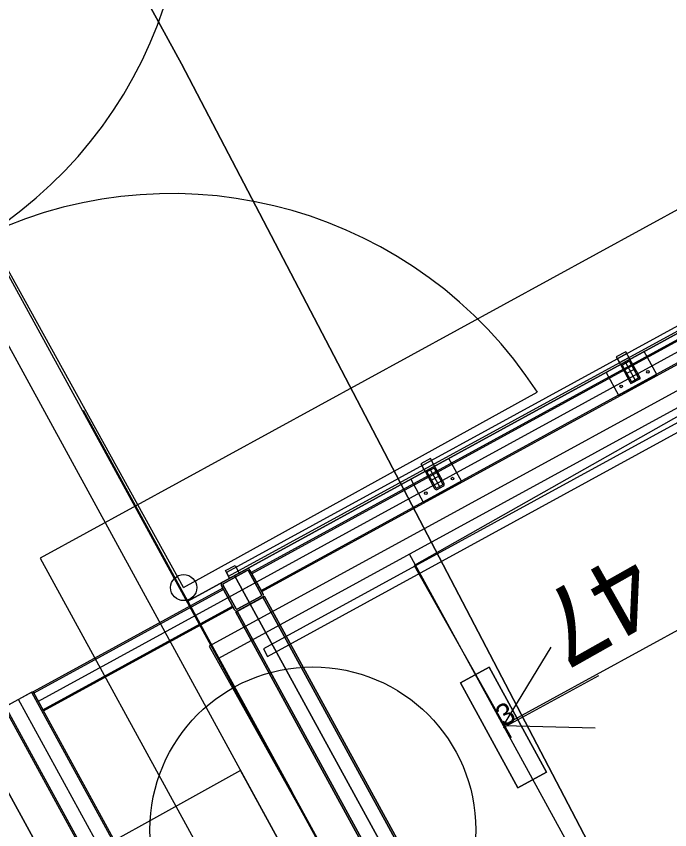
# Model space of a CAD drawing. Extents: x -783978 to -783565, y -1064821 to -1064596.
# Drawn here: x -783787.577 to -783784.57, y -1064693.706 to -1064689.961 of the extents above; entities that cross this region are included whole.
import ezdxf

# ---------------------------------------------------------------- set-up
doc = ezdxf.new("R2010")
doc.units = 0
for name, color, linetype in [('Default', 7, 'Continuous'), ('PS 01_01_10', 7, 'Continuous'), ('PS 01_02_501', 7, 'Continuous'), ('PS 01_02_502', 7, 'Continuous'), ('SO 01_20_01', 7, 'Continuous'), ('SO 01_50_01', 7, 'Continuous'), ('SO 01_74_01', 7, 'Continuous'), ('SO 01_79_02', 7, 'Continuous'), ('SO 01_86_03', 7, 'Continuous'), ('SO 01_86_04', 7, 'Continuous')]:
    doc.layers.add(name, color=color, linetype=linetype)

# ---------------------------------------------------------------- blocks, each defined once
blk = doc.blocks.new('POINT_DISPLAY')
at = {"layer": 'Default'}
blk.add_line((0, 0), (0, 0), dxfattribs=at)

msp = doc.modelspace()

# ---------------------------------------------------------------- linework, layer by layer
at = {"layer": 'PS 01_01_10'}
msp.add_lwpolyline([(-783718.9415, -1064658.9356), (-783725.9639, -1064662.6889), (-783732.3538, -1064665.9121), (-783735.2095, -1064660.6967), (-783789.362, -1064690.3481), (-783783.8255, -1064700.4409), (-783871.4362, -1064748.4249), (-783875.857, -1064749.8347)], dxfattribs=at)
at = {"layer": 'PS 01_02_501'}
msp.add_lwpolyline([(-783952.3105, -1064789.972), (-783925.027, -1064771.233), (-783922.857, -1064767.935), (-783921.1315, -1064767.225), (-783922.344, -1064769.056), (-783920.816, -1064771.043), (-783917.67, -1064770.417), (-783911.05, -1064766.471), (-783887.429, -1064753.525), (-783871.4362, -1064748.4249), (-783783.8277, -1064700.4386), (-783789.362, -1064690.3481), (-783735.2263, -1064660.7067), (-783727.1901, -1064659.072), (-783724.297, -1064658.4835), (-783715.521, -1064653.988), (-783697.391, -1064644.148), (-783676.268, -1064633.506), (-783655.138, -1064621.894)], dxfattribs=at)
at = {"layer": 'PS 01_02_502'}
msp.add_lwpolyline([(-783952.3105, -1064789.972), (-783925.027, -1064771.233), (-783922.857, -1064767.935), (-783921.1315, -1064767.225), (-783922.344, -1064769.056), (-783920.816, -1064771.043), (-783917.67, -1064770.417), (-783911.05, -1064766.471), (-783887.429, -1064753.525), (-783871.4362, -1064748.4249), (-783783.8277, -1064700.4386), (-783789.362, -1064690.3481), (-783735.2263, -1064660.7067), (-783727.1901, -1064659.072), (-783724.297, -1064658.4835), (-783715.521, -1064653.988), (-783697.391, -1064644.148), (-783676.268, -1064633.506), (-783655.138, -1064621.894)], dxfattribs=at)
at = {"layer": 'SO 01_20_01'}
for p, q in [((-783735.0054, -1064663.7532), (-783787.4671, -1064692.4555)), ((-783735.2041, -1064664.4318), (-783786.7885, -1064692.6541)), ((-783786.6445, -1064692.9173), (-783735.3233, -1064664.839)), ((-783738.0171, -1064666.3812), (-783786.4402, -1064692.874)), ((-783786.421, -1064692.9091), (-783737.9979, -1064666.4163)), ((-783737.8741, -1064667.2605), (-783785.3352, -1064693.2269)), ((-783787.4671, -1064692.4555), (-783785.8354, -1064695.4379)), ((-783784.9033, -1064694.0165), (-783785.7672, -1064692.4374)), ((-783786.7885, -1064692.6541), (-783786.6445, -1064692.9173)), ((-783786.4402, -1064692.874), (-783786.421, -1064692.9091)), ((-783785.3352, -1064693.2269), (-783785.1157, -1064692.866)), ((-783785.7805, -1064694.4964), (-783786.6445, -1064692.9173)), ((-783785.3352, -1064693.2269), (-783784.9129, -1064693.2366))]:
    msp.add_line(p, q, dxfattribs=at)
at = {"layer": 'SO 01_50_01'}
for p, q in [((-783786.7885, -1064692.6541), (-783725.4827, -1064659.1131)), ((-783786.7885, -1064692.6541), (-783782.4021, -1064690.2543)), ((-783786.7884, -1064692.6542), (-783782.402, -1064690.2544)), ((-783786.7884, -1064692.6542), (-783782.402, -1064690.2544)), ((-783786.3085, -1064693.5314), (-783787.2685, -1064691.7769))]:
    msp.add_line(p, q, dxfattribs=at)
for points in [[(-783789.5438, -1064687.9418), (-783784.9159, -1064696.417), (-783784.7774, -1064696.3413), (-783789.41, -1064687.8687)], [(-783786.5452, -1064693.4332), (-783787.5293, -1064693.9803), (-783787.1406, -1064694.6795), (-783786.1618, -1064694.1353)]]:
    msp.add_lwpolyline(points, close=True, dxfattribs=at)
msp.add_circle((-783786.2125, -1064693.7069), 0.75, dxfattribs=at)
at = {"layer": 'SO 01_74_01'}
for p, q in [((-783735.2185, -1064664.4055), (-783786.6099, -1064692.5222)), ((-783786.6003, -1064692.5398), (-783735.2089, -1064664.423)), ((-783783.9297, -1064691.1186), (-783786.4958, -1064692.5225)), ((-783783.9267, -1064691.1241), (-783786.4927, -1064692.528)), ((-783786.4508, -1064692.6047), (-783783.8847, -1064691.2008)), ((-783786.4478, -1064692.6102), (-783783.8817, -1064691.2063)), ((-783784.7724, -1064691.5055), (-783784.8162, -1064691.5295)), ((-783784.8162, -1064691.5295), (-783784.7971, -1064691.5646)), ((-783784.7676, -1064691.5143), (-783784.8115, -1064691.5383)), ((-783784.8019, -1064691.5558), (-783784.758, -1064691.5318)), ((-783784.7532, -1064691.5406), (-783784.7724, -1064691.5055)), ((-783784.758, -1064691.5318), (-783784.7676, -1064691.5143)), ((-783784.8115, -1064691.5383), (-783784.8019, -1064691.5558)), ((-783784.7971, -1064691.5646), (-783784.7532, -1064691.5406)), ((-783785.6716, -1064691.9975), (-783785.7155, -1064692.0215)), ((-783785.6668, -1064692.0063), (-783785.7107, -1064692.0303)), ((-783785.6524, -1064692.0326), (-783785.6716, -1064691.9975)), ((-783785.6572, -1064692.0238), (-783785.6668, -1064692.0063)), ((-783785.7155, -1064692.0215), (-783785.6963, -1064692.0566)), ((-783785.7107, -1064692.0303), (-783785.7011, -1064692.0478)), ((-783785.7011, -1064692.0478), (-783785.6572, -1064692.0238)), ((-783785.6963, -1064692.0566), (-783785.6524, -1064692.0326)), ((-783786.6147, -1064692.5135), (-783786.5708, -1064692.4895)), ((-783786.6147, -1064692.5135), (-783786.5708, -1064692.4895)), ((-783786.5708, -1064692.4895), (-783786.5516, -1064692.5245)), ((-783786.5708, -1064692.4895), (-783786.5516, -1064692.5245)), ((-783786.5955, -1064692.5485), (-783786.6147, -1064692.5135)), ((-783786.5955, -1064692.5485), (-783786.6147, -1064692.5135)), ((-783786.6099, -1064692.5222), (-783786.6003, -1064692.5398)), ((-783786.5516, -1064692.5245), (-783786.5955, -1064692.5485)), ((-783786.5516, -1064692.5245), (-783786.5955, -1064692.5485)), ((-783786.4958, -1064692.5225), (-783786.4478, -1064692.6102)), ((-783786.4927, -1064692.528), (-783786.4508, -1064692.6047)), ((-783786.6273, -1064692.5945), (-783787.5002, -1064693.072)), ((-783786.6243, -1064692.6), (-783787.4972, -1064693.0776)), ((-783786.5794, -1064692.6822), (-783786.6273, -1064692.5945)), ((-783786.5824, -1064692.6767), (-783786.6243, -1064692.6)), ((-783786.5674, -1064692.7041), (-783786.4358, -1064692.6321)), ((-783786.4358, -1064692.6321), (-783786.5674, -1064692.7041)), ((-783786.5603, -1064692.7003), (-783786.4428, -1064692.636)), ((-783786.4428, -1064692.636), (-783786.5603, -1064692.7003)), ((-783786.4428, -1064692.636), (-783785.4348, -1064694.4783)), ((-783785.4348, -1064694.4783), (-783786.4428, -1064692.636)), ((-783786.4358, -1064692.6321), (-783785.4278, -1064694.4744)), ((-783785.4278, -1064694.4744), (-783786.4358, -1064692.6321)), ((-783787.4553, -1064693.1542), (-783786.5824, -1064692.6767)), ((-783787.4523, -1064693.1598), (-783786.5794, -1064692.6822)), ((-783785.5594, -1064694.5464), (-783786.5674, -1064692.7041)), ((-783786.5674, -1064692.7041), (-783785.5594, -1064694.5464)), ((-783785.5524, -1064694.5426), (-783786.5603, -1064692.7003)), ((-783786.5603, -1064692.7003), (-783785.5524, -1064694.5426)), ((-783787.6328, -1064693.1424), (-783787.5012, -1064693.0704)), ((-783787.6272, -1064693.1393), (-783787.5067, -1064693.0734)), ((-783787.5067, -1064693.0734), (-783786.3776, -1064695.1372)), ((-783787.5012, -1064693.0704), (-783786.372, -1064695.1342)), ((-783787.5002, -1064693.072), (-783787.4523, -1064693.1598)), ((-783787.4972, -1064693.0776), (-783787.4553, -1064693.1542)), ((-783786.5036, -1064695.2062), (-783787.6328, -1064693.1424)), ((-783786.4981, -1064695.2032), (-783787.6272, -1064693.1393))]:
    msp.add_line(p, q, dxfattribs=at)
for points in [[(-783735.1681, -1064664.4976), (-783787.4762, -1064693.1159)], [(-783784.7615, -1064691.5451), (-783784.7888, -1064691.5601)], [(-783784.787, -1064691.5699), (-783784.7481, -1064691.641)], [(-783784.7585, -1064691.5507), (-783784.7857, -1064691.5656)], [(-783784.7751, -1064691.5526), (-783784.7271, -1064691.6403)], [(-783784.7153, -1064691.6231), (-783784.7542, -1064691.5519)], [(-783784.7097, -1064691.62), (-783784.7487, -1064691.5489)], [(-783784.7925, -1064691.5729), (-783784.7536, -1064691.644)], [(-783784.7292, -1064691.5845), (-783784.7731, -1064691.6085)], [(-783784.7438, -1064691.6423), (-783784.7165, -1064691.6273)], [(-783784.7408, -1064691.6478), (-783784.7135, -1064691.6329)], [(-783785.6607, -1064692.0371), (-783785.688, -1064692.052)], [(-783785.6577, -1064692.0426), (-783785.685, -1064692.0576)], [(-783785.6743, -1064692.0446), (-783785.6263, -1064692.1323)], [(-783785.6145, -1064692.115), (-783785.6534, -1064692.0439)], [(-783785.6089, -1064692.112), (-783785.6479, -1064692.0409)], [(-783785.6917, -1064692.0649), (-783785.6528, -1064692.136)], [(-783785.6862, -1064692.0618), (-783785.6473, -1064692.133)], [(-783785.6284, -1064692.0764), (-783785.6723, -1064692.1004)], [(-783785.643, -1064692.1342), (-783785.6157, -1064692.1193)], [(-783785.64, -1064692.1398), (-783785.6127, -1064692.1248)], [(-783786.5183, -1064692.5063), (-783786.6288, -1064692.5668)], [(-783786.6288, -1064692.5668), (-783786.5183, -1064692.5063)], [(-783786.5144, -1064692.5133), (-783786.625, -1064692.5738)], [(-783786.625, -1064692.5738), (-783786.5144, -1064692.5133)], [(-783785.4216, -1064694.642), (-783786.5736, -1064692.5365)], [(-783786.5736, -1064692.5365), (-783785.4216, -1064694.642)], [(-783786.5736, -1064692.5365), (-783786.5016, -1064692.6681)], [(-783786.4485, -1064692.6255), (-783786.509, -1064692.5149)], [(-783786.509, -1064692.5149), (-783786.4485, -1064692.6255)], [(-783786.4415, -1064692.6216), (-783786.502, -1064692.5111)], [(-783786.502, -1064692.5111), (-783786.4415, -1064692.6216)], [(-783786.6266, -1064692.5792), (-783786.5661, -1064692.6898)], [(-783786.5661, -1064692.6898), (-783786.6266, -1064692.5792)], [(-783786.4718, -1064692.5663), (-783786.6034, -1064692.6383)], [(-783786.6336, -1064692.5831), (-783786.5731, -1064692.6936)], [(-783786.5731, -1064692.6936), (-783786.6336, -1064692.5831)], [(-783786.5607, -1064692.6914), (-783786.4501, -1064692.6309)], [(-783786.4501, -1064692.6309), (-783786.5607, -1064692.6914)], [(-783786.5568, -1064692.6984), (-783786.4463, -1064692.6379)], [(-783786.4463, -1064692.6379), (-783786.5568, -1064692.6984)], [(-783786.4378, -1064695.1702), (-783787.567, -1064693.1064)]]:
    msp.add_lwpolyline(points, dxfattribs=at)
for points in [[(-783784.6874, -1064691.5046), (-783784.8628, -1064691.6006), (-783784.8053, -1064691.7059), (-783784.6298, -1064691.6099)], [(-783784.7532, -1064691.5406), (-783784.7971, -1064691.5646), (-783784.7491, -1064691.6523), (-783784.7052, -1064691.6283)], [(-783785.5866, -1064691.9966), (-783785.7621, -1064692.0926), (-783785.7045, -1064692.1978), (-783785.529, -1064692.1019)]]:
    msp.add_lwpolyline(points, close=True, dxfattribs=at)
for centre in [(-783784.6705, -1064691.598), (-783784.7933, -1064691.6652), (-783785.5697, -1064692.0899), (-783785.6925, -1064692.1571)]:
    msp.add_circle(centre, 0.006, dxfattribs=at)
for centre, radius, start, end in [((-783784.7842, -1064691.5684), 0.00945, 118.6835, 208.6835), ((-783784.7842, -1064691.5684), 0.00315, 118.6835, 208.6835), ((-783784.7569, -1064691.5534), 0.00945, 28.6835, 118.6835), ((-783784.7569, -1064691.5534), 0.00315, 28.6835, 118.6835), ((-783784.7453, -1064691.6395), 0.00945, 208.6835, 298.6835), ((-783784.7453, -1064691.6395), 0.00315, 208.6835, 298.6835), ((-783784.718, -1064691.6246), 0.00315, 298.6835, 28.6835), ((-783784.718, -1064691.6246), 0.00945, 298.6835, 28.6835), ((-783785.6834, -1064692.0603), 0.00945, 118.6835, 208.6835), ((-783785.6834, -1064692.0603), 0.00315, 118.6835, 208.6835), ((-783785.6562, -1064692.0454), 0.00945, 28.6835, 118.6835), ((-783785.6562, -1064692.0454), 0.00315, 28.6835, 118.6835), ((-783785.6172, -1064692.1165), 0.00315, 298.6835, 28.6835), ((-783785.6172, -1064692.1165), 0.00945, 298.6835, 28.6835), ((-783785.6445, -1064692.1315), 0.00945, 208.6835, 298.6835), ((-783785.6445, -1064692.1315), 0.00315, 208.6835, 298.6835), ((-783786.5125, -1064692.5168), 0.012, 28.6835, 118.6835), ((-783786.5125, -1064692.5168), 0.012, 28.6835, 118.6835), ((-783786.5125, -1064692.5168), 0.004, 28.6835, 118.6835), ((-783786.5125, -1064692.5168), 0.004, 28.6835, 118.6835), ((-783786.6231, -1064692.5773), 0.012, 118.6835, 208.6835), ((-783786.6231, -1064692.5773), 0.012, 118.6835, 208.6835), ((-783786.6231, -1064692.5773), 0.004, 118.6835, 208.6835), ((-783786.6231, -1064692.5773), 0.004, 118.6835, 208.6835), ((-783786.452, -1064692.6274), 0.004, 298.6835, 28.6835), ((-783786.452, -1064692.6274), 0.004, 298.6835, 28.6835), ((-783786.452, -1064692.6274), 0.012, 298.6835, 28.6835), ((-783786.452, -1064692.6274), 0.012, 298.6835, 28.6835), ((-783786.5626, -1064692.6878), 0.012, 208.6835, 298.6835), ((-783786.5626, -1064692.6878), 0.012, 208.6835, 298.6835), ((-783786.5626, -1064692.6878), 0.004, 208.6835, 298.6835), ((-783786.5626, -1064692.6878), 0.004, 208.6835, 298.6835)]:
    msp.add_arc(centre, radius, start, end, dxfattribs=at)
at = {"layer": 'SO 01_79_02'}
for q in [(-783788.6076, -1064689.3366), (-783785.1795, -1064691.6915)]:
    msp.add_line((-783786.8071, -1064692.5918), q, dxfattribs=at)
msp.add_circle((-783786.8071, -1064692.5918), 0.06, dxfattribs=at)
for centre, start, end in [((-783788.8009, -1064689.281), 303.0113, 24.8851), ((-783786.8627, -1064692.7851), 33.0113, 114.8851)]:
    msp.add_arc(centre, 2.0073, start, end, dxfattribs=at)
at = {"layer": 'SO 01_86_03'}
msp.add_line((-783783.3595, -1064696.8031), (-783786.8168, -1064690.1799), dxfattribs=at)
for points in [[(-783722.5212, -1064661.7932), (-783724.8208, -1064663.0486), (-783735.2095, -1064660.6967), (-783787.333, -1064689.2371), (-783786.8168, -1064690.1799), (-783783.3595, -1064696.8031), (-783781.9388, -1064699.4088), (-783783.8277, -1064700.4386), (-783871.4362, -1064748.4249), (-783875.857, -1064749.8347), (-783877.5381, -1064747.3925), (-783875.857, -1064749.8347), (-783887.429, -1064753.525), (-783911.05, -1064766.471), (-783917.67, -1064770.417), (-783920.816, -1064771.043), (-783922.344, -1064769.056), (-783922.498, -1064767.051)], [(-783747.0305, -1064676.621), (-783747.6236, -1064677.108), (-783750.7299, -1064678.7824), (-783751.6662, -1064678.8522), (-783782.6812, -1064695.8307), (-783782.8877, -1064696.6917), (-783783.0615, -1064696.8198), (-783783.3595, -1064696.8031), (-783786.8168, -1064690.1799), (-783787.333, -1064689.2371), (-783735.2095, -1064660.6967), (-783724.8208, -1064663.0486), (-783722.5212, -1064661.7932)]]:
    msp.add_lwpolyline(points, dxfattribs=at)
at = {"layer": 'SO 01_86_04'}
for p, q in [((-783785.747, -1064692.4898), (-783785.2993, -1064693.2823)), ((-783785.4018, -1064692.9585), (-783785.5334, -1064693.0305)), ((-783785.4018, -1064692.9585), (-783785.5334, -1064693.0305)), ((-783785.5334, -1064693.0305), (-783785.4018, -1064692.9585)), ((-783785.5334, -1064693.0305), (-783785.4018, -1064692.9585)), ((-783785.1378, -1064693.441), (-783785.4018, -1064692.9585)), ((-783785.1378, -1064693.441), (-783785.4018, -1064692.9585)), ((-783785.4018, -1064692.9585), (-783785.1378, -1064693.441)), ((-783785.4018, -1064692.9585), (-783785.1378, -1064693.441)), ((-783785.5334, -1064693.0305), (-783785.2694, -1064693.513)), ((-783785.5334, -1064693.0305), (-783785.2694, -1064693.513)), ((-783785.2694, -1064693.513), (-783785.5334, -1064693.0305)), ((-783785.2694, -1064693.513), (-783785.5334, -1064693.0305)), ((-783785.3356, -1064693.2358), (-783784.8969, -1064692.9958)), ((-783785.2694, -1064693.513), (-783785.1378, -1064693.441)), ((-783785.2694, -1064693.513), (-783785.1378, -1064693.441)), ((-783785.1378, -1064693.441), (-783785.2694, -1064693.513)), ((-783785.1378, -1064693.441), (-783785.2694, -1064693.513))]:
    msp.add_line(p, q, dxfattribs=at)
for points in [[(-783738.3222, -1064666.4797), (-783740.5325, -1064667.689), (-783743.1715, -1064669.1328), (-783745.7538, -1064670.5456), (-783748.4385, -1064672.0145), (-783751.0413, -1064673.4385), (-783753.6847, -1064674.8847), (-783756.3281, -1064676.3309), (-783758.9715, -1064677.7772), (-783761.6149, -1064679.2234), (-783764.2583, -1064680.6696), (-783766.9018, -1064682.1159), (-783769.4633, -1064683.5173), (-783772.109, -1064684.9648), (-783774.7882, -1064686.4306), (-783778.1382, -1064688.2722), (-783783.8139, -1064691.3971), (-783785.747, -1064692.4898)], [(-783747.063, -1064670.9765), (-783746.9575, -1064671.1681), (-783786.6893, -1064692.8619), (-783786.185, -1064693.7636)]]:
    msp.add_lwpolyline(points, dxfattribs=at)

# ---------------------------------------------------------------- block references
at = {"layer": 'SO 01_86_04', "xscale": 0.010000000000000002, "yscale": 0.009999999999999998, "rotation": 28.683491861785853}
for p in [(-783785.4018, -1064692.9585), (-783785.4018, -1064692.9585), (-783785.5334, -1064693.0305), (-783785.5334, -1064693.0305), (-783785.1378, -1064693.441), (-783785.1378, -1064693.441), (-783785.2694, -1064693.513), (-783785.2694, -1064693.513)]:
    msp.add_blockref('POINT_DISPLAY', p, dxfattribs=at)

# ---------------------------------------------------------------- texts
at = {"layer": 'SO 01_86_04'}
for s, height, rotation, p in [('47', 0.351, 209.46, (-783784.7572, -1064692.4095)), ('3', 0.1, 28.6835, (-783785.3356, -1064693.2358))]:
    msp.add_text(s, height=height, rotation=rotation, dxfattribs=at).set_placement(p)

doc.saveas('drawing.dxf')
